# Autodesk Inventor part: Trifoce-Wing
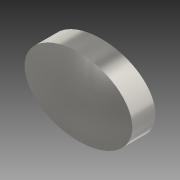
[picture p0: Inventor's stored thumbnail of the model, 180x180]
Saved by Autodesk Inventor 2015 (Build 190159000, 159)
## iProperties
Created: 2017-03
Part Number: Trifoce-Wing
Material: Generisch
Document SubType Name: Modeling
Designer: Andreas
Density: 1 g/cm^3
Appearance: Vorgabe
Author: Andreas
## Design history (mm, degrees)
sketch "Skizze1"
  geometry: L1 (0, 0)-(46.228, 0); L2 (46.228, 0)-(46.228, -29.041); L3 (46.228, -29.041)-(0, -29.041); L4 (0, -29.041)-(0, 0); L5 (45.49, -0.497)-(45.409, -4.653); L6 (45.409, -4.653)-(31.088, -5.681); L7 (45.49, -0.497)-(29.627, -3.829); L8 (44.569, -7.318)-(31.571, -7.436); L9 (44.569, -7.318)-(41.625, -11.982); L10 (41.625, -11.982)-(31.586, -9.1); L11 (39.653, -13.986)-(35.574, -16.764); L12 (35.574, -16.764)-(30.081, -12.947); L13 (30.986, -11.331)-(39.653, -13.986); L14 (28.52, -14.685)-(32.409, -17.996); L15 (32.409, -17.996)-(29.292, -19.158); L16 (29.292, -19.158)-(27.212, -15.344); L17 (25.736, -14.607)-(26.547, -15.797); A1 r 7.384 centre (22.936, -7.775) between (25.736, -14.607) and (27.306, -1.822); A2 r 4.794 centre (25.496, -6.261) between (29.627, -3.829) and (27.306, -1.822); A3 r 6.557 centre (25.069, -8.282) between (31.571, -7.436) and (31.088, -5.681); A4 r 3.534 centre (28.061, -9.347) between (30.986, -11.331) and (31.586, -9.1); A5 r 6.375 centre (24.638, -9.629) between (28.52, -14.685) and (30.081, -12.947); A6 r 2.099 centre (25.72, -13.868) between (26.547, -15.797) and (27.212, -15.344); 1 other entity
  constraints: 26 end point, 12 point on circle, 6 centre point, 2 other
  node "Bild1"
sketch "Skizze2"
  geometry: L1 (23.042, -1.191)-(28.644, -10.954); L2 (28.644, -10.954)-(17.346, -10.954); L3 (17.346, -10.954)-(23.042, -1.191); L4 (25.8, -5.996)-(20.238, -5.996); L5 (20.238, -5.996)-(22.995, -10.954); L6 (25.8, -5.996)-(22.995, -10.954); 1 further point
  constraints: 12 end point, 2 point on line, 1 horizontal, 1 midpoint, 1 parallel
sketch "Skizze3"
  geometry: L1 (25.67, -17.011)-(23.02, -12.436); L2 (23.02, -12.436)-(20.253, -17.012); L3 (20.253, -17.012)-(20.253, -17.246); L4 (25.67, -17.011)-(25.67, -17.246); L5 (22.387, -19.084)-(22.387, -20.045); L6 (23.603, -19.038)-(23.603, -19.934); 48 further points
  constraints: 12 end point, 4 vertical, 56 other
sketch "Skizze4"
  geometry: L1 (16.283, -3.828)-(15.91, -3.828); L2 (15.91, -3.828)-(0.472, -0.505); L3 (0.472, -0.505)-(0.505, -4.576); L4 (0.505, -4.576)-(14.837, -5.726); L5 (14.386, -7.44)-(1.341, -7.303); L6 (1.341, -7.303)-(4.287, -11.939); L7 (4.287, -11.939)-(14.309, -9.096); L8 (14.877, -11.311)-(6.275, -13.936); L9 (6.275, -13.936)-(10.315, -16.693); L10 (10.315, -16.693)-(15.754, -12.97); L11 (17.408, -14.691)-(13.45, -18.012); L12 (13.45, -18.012)-(16.586, -19.16); L13 (16.586, -19.16)-(18.665, -15.382); L14 (19.412, -15.793)-(20.107, -14.519); A1 r 2.257 centre (20.107, -13.646) between (18.665, -15.382) and (19.412, -15.793); A2 r 6.936 centre (21.506, -9.096) between (15.754, -12.97) and (17.408, -14.691); A3 r 4.051 centre (18.358, -9.238) between (14.309, -9.096) and (14.877, -11.311); A4 r 4.758 centre (19.132, -7.774) between (14.837, -5.726) and (14.386, -7.44); A5 r 5.356 centre (20.794, -6.714) between (18.304, -1.972) and (16.283, -3.828); A6 r 7.407 centre (23.001, -7.7) between (18.304, -1.972) and (20.107, -14.519); 1 further point
  constraints: 28 end point, 12 point on circle, 6 centre point, 1 horizontal
sketch "Skizze5"
  geometry: L1 (13.705, -21.546)-(17.832, -21.546); L2 (17.832, -21.546)-(18.394, -18.463); L3 (18.394, -18.463)-(19.052, -18.207); L4 (19.052, -18.207)-(19.569, -18.207); L5 (19.569, -18.207)-(20.059, -18.666); L6 (20.059, -18.666)-(20.059, -18.891); L7 (20.059, -18.891)-(18.809, -21.52); L8 (18.809, -21.52)-(18.809, -21.873); L9 (18.809, -21.873)-(19.178, -22.822); L10 (19.178, -22.822)-(19.178, -23.15); L11 (19.178, -23.15)-(17.54, -24.458); L12 (17.54, -24.458)-(17.501, -24.358); L13 (17.501, -24.358)-(17.98, -22.881); L14 (17.98, -22.881)-(17.98, -22.715); L15 (17.98, -22.715)-(14.374, -23.269); L16 (14.374, -23.269)-(14.374, -23.472); L17 (14.374, -23.472)-(15.598, -27.94); L18 (15.598, -27.94)-(12.704, -23.6); L19 (12.704, -23.6)-(12.775, -22.255); L20 (12.775, -22.255)-(13.705, -21.546); 1 further point
  constraints: 40 end point, 4 parallel, 2 vertical, 1 horizontal, 1 perpendicular
sketch "Skizze6"
  geometry: L1 (26.478, -18.092)-(26.691, -18.092); L2 (26.691, -18.092)-(27.628, -18.497); L3 (27.628, -18.497)-(28.135, -21.51); L4 (28.135, -21.51)-(32.232, -21.51); L5 (32.232, -21.51)-(33.17, -22.271); L6 (33.17, -22.271)-(33.225, -22.996); L7 (30.333, -28.028)-(33.197, -23.765); L8 (30.333, -28.028)-(31.606, -23.414); L9 (31.606, -23.414)-(31.606, -23.313); L10 (31.606, -23.313)-(27.91, -22.687); L11 (27.91, -22.687)-(28.549, -24.502); L12 (28.549, -24.502)-(28.37, -24.502); L13 (28.37, -24.502)-(26.691, -23.094); L14 (26.691, -23.094)-(27.16, -21.846); L15 (27.16, -21.846)-(27.16, -21.584); L16 (27.16, -21.584)-(25.882, -18.754); L17 (25.882, -18.754)-(26.478, -18.092); A1 r 1.339 centre (31.929, -23.334) between (33.197, -23.765) and (33.225, -22.996); 1 further point
  constraints: 34 end point, 2 perpendicular, 2 point on circle, 1 centre point, 1 horizontal, 1 parallel, 1 vertical
extrude "Extrusion1" new body sketch "Skizze4" distance "d13" = 10; taper "d14" = 0 deg
extrude "Extrusion2" join sketch "Skizze2" distance "d16" = 10; taper "d17" = 0 deg
extrude "Extrusion3" join sketch "Skizze3" distance "d18" = 10; taper "d19" = 0 deg
extrude "Extrusion4" join sketch "Skizze5" distance "d20" = 10; taper "d21" = 0 deg
extrude "Extrusion5" join sketch "Skizze6" distance "d22" = 10; taper "d23" = 0 deg
extrude "Extrusion6" join sketch "Skizze1" distance "d24" = 10; taper "d25" = 0 deg
sketch "Skizze7" dims "d28" = 35, "d29" = 25
  geometry: 3 further points; 1 other entity
  constraints: 1 coincident, 2 other
extrude "Extrusion7" join sketch "Skizze7" distance "d30" = 5; taper "d31" = 0 deg
sketch "Skizze8" dims "d32" = 3
  geometry: L1 (-26.691, 18.092)-(-27.628, 18.497) reference; L2 (-27.628, 18.497)-(-28.135, 21.51) reference; L3 (-28.135, 21.51)-(-32.232, 21.51) reference; L4 (-32.232, 21.51)-(-33.17, 22.271) reference; L5 (-33.17, 22.271)-(-33.225, 22.996) reference; L6 (-33.197, 23.765)-(-30.333, 28.028) reference; L7 (-30.333, 28.028)-(-31.606, 23.414) reference; L8 (-31.606, 23.414)-(-31.606, 23.313) reference; L9 (-31.606, 23.313)-(-27.91, 22.687) reference; L10 (-27.91, 22.687)-(-28.549, 24.502) reference; L11 (-28.549, 24.502)-(-28.37, 24.502) reference; L12 (-28.37, 24.502)-(-26.691, 23.094) reference; L13 (-26.691, 23.094)-(-27.16, 21.846) reference; L14 (-27.16, 21.846)-(-27.16, 21.584) reference; L15 (-27.16, 21.584)-(-25.882, 18.754) reference; L16 (-25.882, 18.754)-(-26.478, 18.092) reference; L17 (-26.478, 18.092)-(-26.691, 18.092) reference; L18 (-25.67, 17.246)-(-25.67, 17.011) reference; L19 (-23.603, 19.934)-(-23.603, 19.038) reference; L20 (-22.387, 19.084)-(-22.387, 20.045) reference; L21 (-20.253, 17.012)-(-20.253, 17.246) reference; L22 (-23.02, 12.436)-(-20.253, 17.012) reference; L23 (-25.67, 17.011)-(-23.02, 12.436) reference; L24 (-19.412, 15.793)-(-20.107, 14.519) reference; L25 (-16.586, 19.16)-(-18.665, 15.382) reference; L26 (-13.45, 18.012)-(-16.586, 19.16) reference; L27 (-17.408, 14.691)-(-13.45, 18.012) reference; L28 (-10.315, 16.693)-(-15.754, 12.97) reference; L29 (-6.275, 13.936)-(-10.315, 16.693) reference; L30 (-14.877, 11.311)-(-6.275, 13.936) reference; L31 (-4.287, 11.939)-(-14.309, 9.096) reference; L32 (-1.341, 7.303)-(-4.287, 11.939) reference; L33 (-14.386, 7.44)-(-1.341, 7.303) reference; L34 (-0.505, 4.576)-(-14.837, 5.726) reference; L35 (-0.472, 0.505)-(-0.505, 4.576) reference; L36 (-15.91, 3.828)-(-0.472, 0.505) reference; L37 (-16.283, 3.828)-(-15.91, 3.828) reference; L38 (-20.238, 5.996)-(-17.346, 10.954) reference; L39 (-23.042, 1.191)-(-20.238, 5.996) reference; L40 (-25.8, 5.996)-(-23.042, 1.191) reference; L41 (-28.644, 10.954)-(-25.8, 5.996) reference; L42 (-22.995, 10.954)-(-28.644, 10.954) reference; L43 (-17.346, 10.954)-(-22.995, 10.954) reference; L44 (-17.832, 21.546)-(-18.394, 18.463) reference; L45 (-18.394, 18.463)-(-19.052, 18.207) reference; L46 (-19.052, 18.207)-(-19.569, 18.207) reference; L47 (-19.569, 18.207)-(-20.059, 18.666) reference; L48 (-20.059, 18.666)-(-20.059, 18.891) reference; L49 (-20.059, 18.891)-(-18.809, 21.52) reference; L50 (-18.809, 21.52)-(-18.809, 21.873) reference; L51 (-18.809, 21.873)-(-19.178, 22.822) reference; L52 (-19.178, 22.822)-(-19.178, 23.15) reference; L53 (-19.178, 23.15)-(-17.54, 24.458) reference; L54 (-17.54, 24.458)-(-17.501, 24.358) reference; L55 (-17.501, 24.358)-(-17.98, 22.881) reference; L56 (-17.98, 22.881)-(-17.98, 22.715) reference; L57 (-17.98, 22.715)-(-14.374, 23.269) reference; L58 (-14.374, 23.269)-(-14.374, 23.472) reference; L59 (-14.374, 23.472)-(-15.598, 27.94) reference; L60 (-15.598, 27.94)-(-12.704, 23.6) reference; L61 (-12.704, 23.6)-(-12.775, 22.255) reference; L62 (-12.775, 22.255)-(-13.705, 21.546) reference; L63 (-13.705, 21.546)-(-17.832, 21.546) reference; L64 (-45.409, 4.653)-(-31.088, 5.681) reference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; A1 r 1.339 centre (-31.929, 23.334) between (-33.197, 23.765) and (-33.225, 22.996) reference; A2 r 5.356 centre (-20.794, 6.714) between (-18.304, 1.972) and (-16.283, 3.828) reference; A3 r 7.407 centre (-23.001, 7.7) between (-18.304, 1.972) and (-20.107, 14.519) reference; A4 r 2.257 centre (-20.107, 13.646) between (-18.665, 15.382) and (-19.412, 15.793) reference; A5 r 6.936 centre (-21.506, 9.096) between (-15.754, 12.97) and (-17.408, 14.691) reference; A6 r 4.051 centre (-18.358, 9.238) between (-14.309, 9.096) and (-14.877, 11.311) reference; A7 r 4.758 centre (-19.132, 7.774) between (-14.837, 5.726) and (-14.386, 7.44) reference; A8 r 6.557 centre (-25.069, 8.282) between (-31.571, 7.436) and (-31.088, 5.681) reference; A9 r 3.534 centre (-28.061, 9.347) between (-30.986, 11.331) and (-31.586, 9.1) reference; A10 r 6.375 centre (-24.638, 9.629) between (-28.52, 14.685) and (-30.081, 12.947) reference; A11 r 2.099 centre (-25.72, 13.868) between (-26.547, 15.797) and (-27.212, 15.344) reference; A12 r 7.384 centre (-22.936, 7.775) between (-25.736, 14.607) and (-27.306, 1.822) reference; A13 r 4.794 centre (-25.496, 6.261) between (-29.627, 3.829) and (-27.306, 1.822) reference; 5 further points; 1 other entity
  constraints: 7 other
extrude "Extrusion8" join sketch "Skizze8" distance "d33" = 10; taper "d34" = 0 deg
node "Volumenkörper1"
node "Projizierte Kontur1"
